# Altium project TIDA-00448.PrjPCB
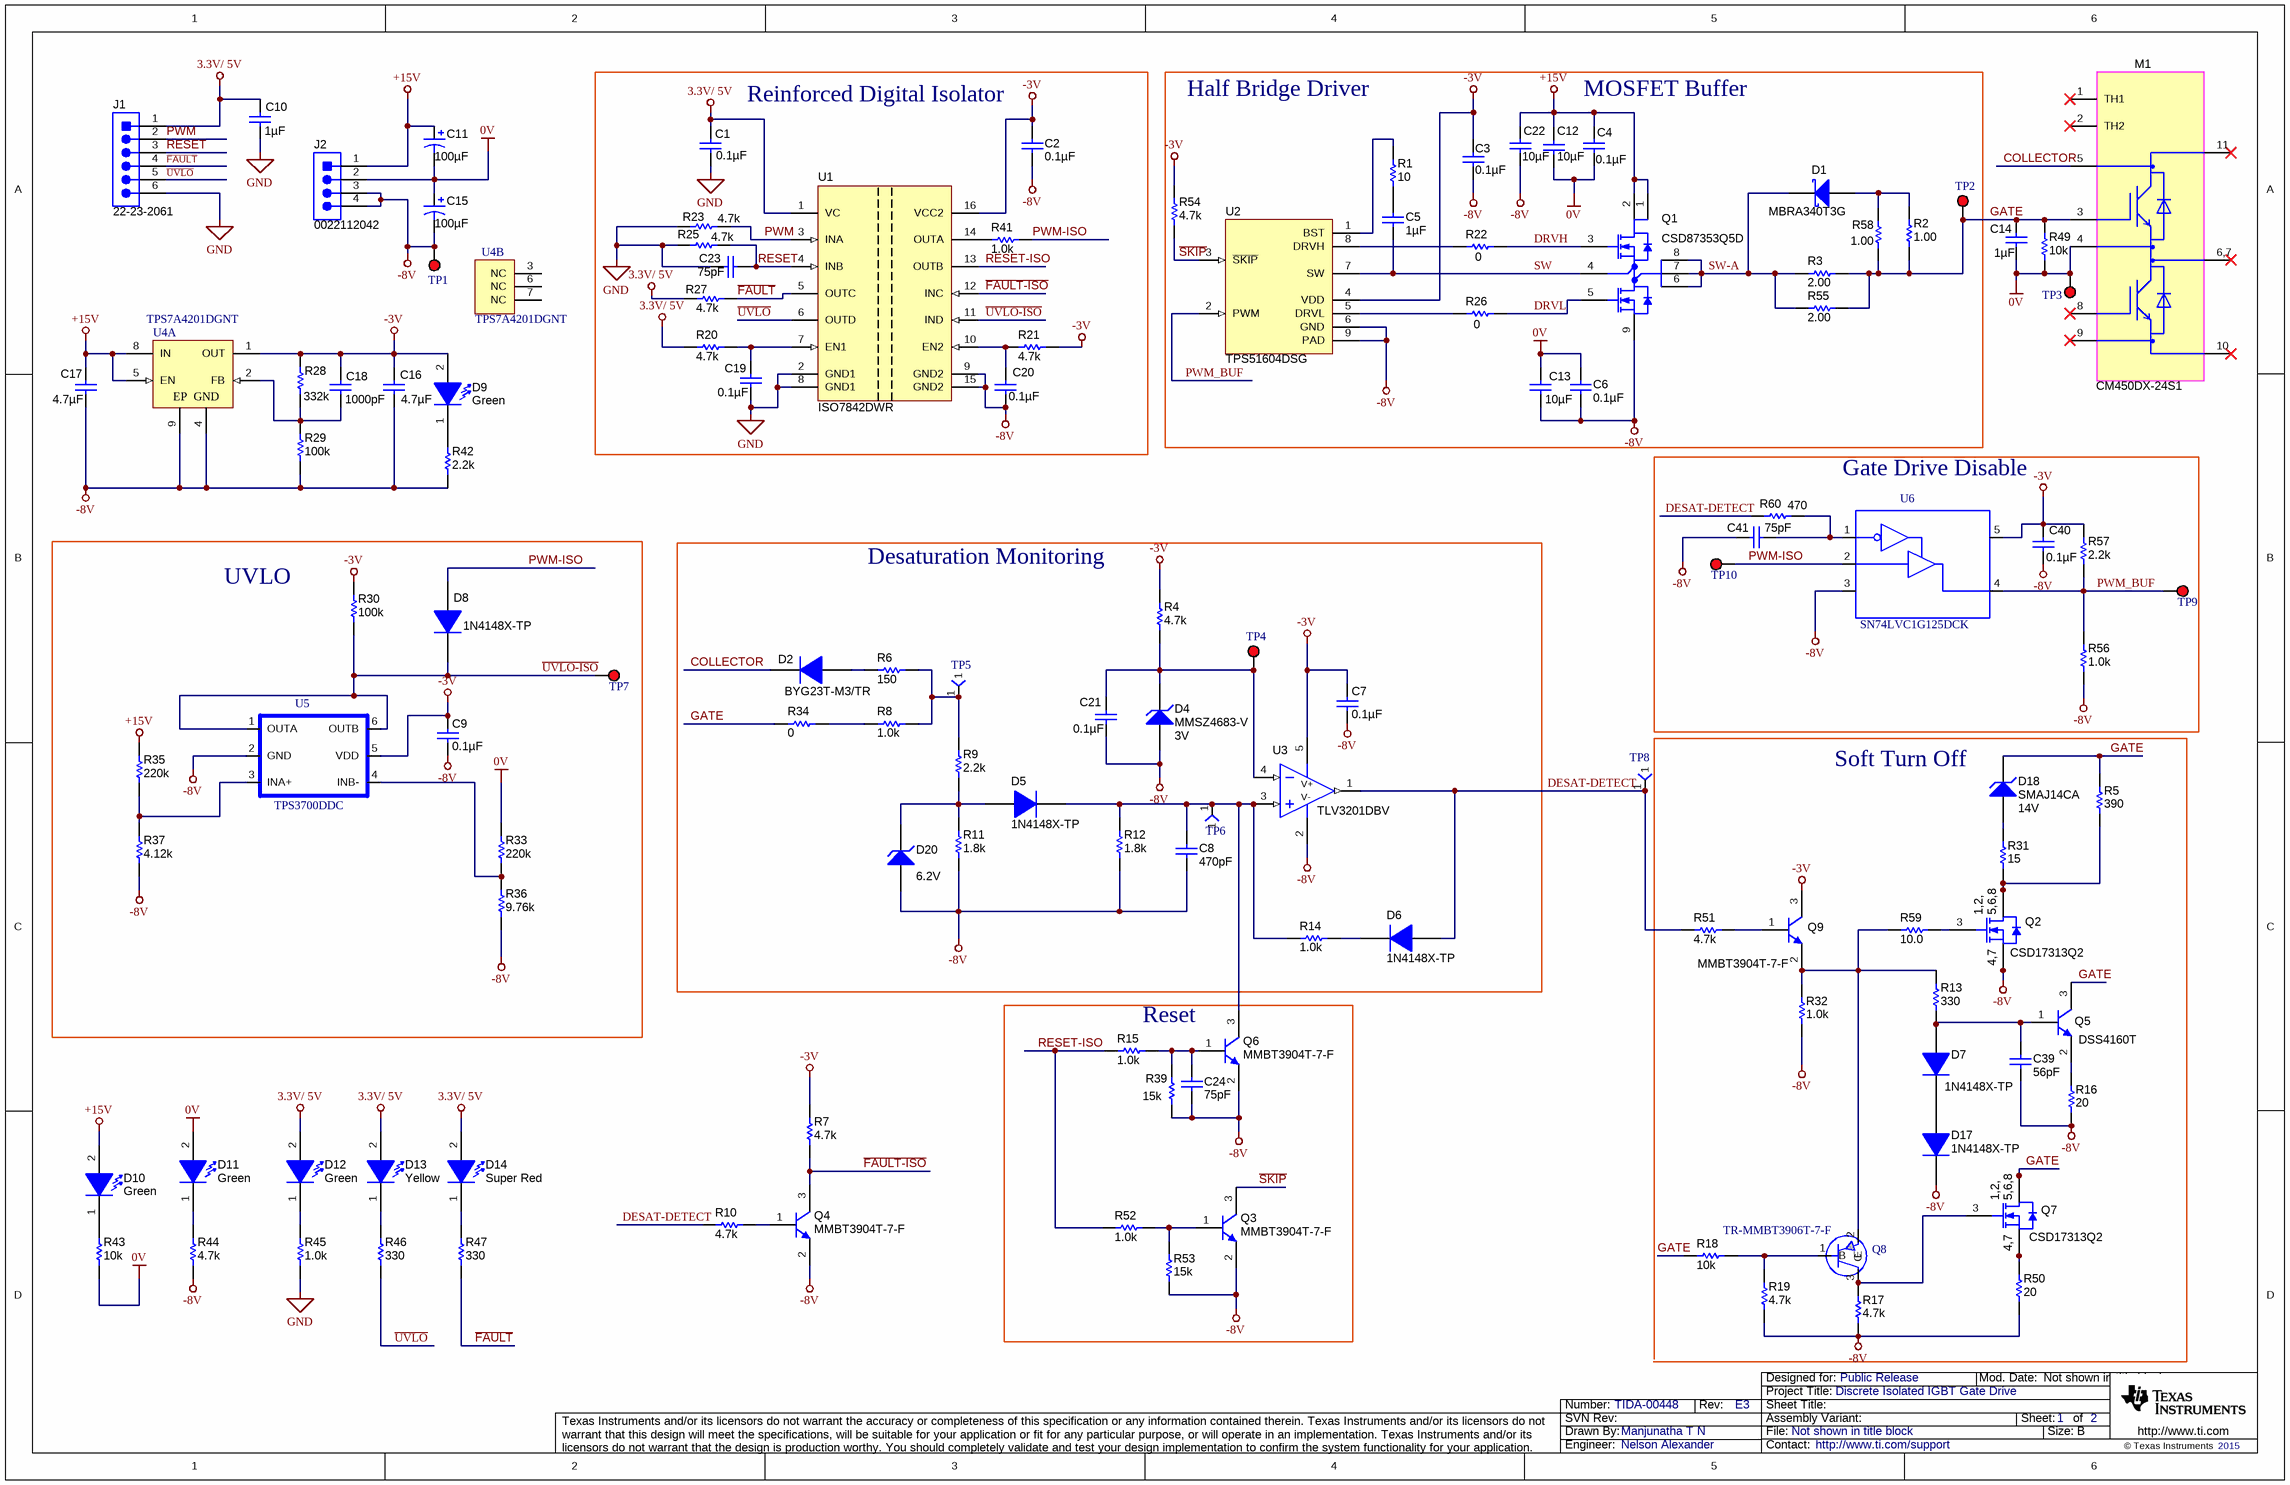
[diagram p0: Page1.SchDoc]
CopyrightYear: 2015; PCB_Layout: Manjunatha T N; PCB_Rev: E3; PRJ_Customer: Public Release; PRJ_Engineer: Nelson Alexander; PRJ_Number: TIDA-00448; PRJ_Title: Discrete Isolated IGBT Gate Drive; SCH_Rev: E3; TechSupport: http://www.ti.com/support
2 sheets, 141 parts. Net scope: global (net labels, ports and power ports of the same name join across sheets).
Board file: TIDA-00448_E3.PcbDoc
Sheets:
  Page1.SchDoc
  Page2_Hardware_ANSI-B.SchDoc

## Sheet Page1.SchDoc
size 431 x 279 mm; Date: Not shown in title block; ApprovedBy: Not shown in title block; CheckedBy: Not shown in title block; Author: Not shown in title block; CompanyName: Not shown in title block; DrawnBy: Manjunatha T N; Engineer: Not shown in title block; Organization: Not shown in title block; Address1: Not shown in title block; Address2: Not shown in title block; Address3: Not shown in title block; Address4: Not shown in title block; DocumentNumber: 4; Revision: Use project parameter SCH_Rev; SheetNumber: 1; SheetTotal: 2; PageSetup: Record=PageOptions¦CenterHorizontal=True¦CenterVertical=True¦PrintScale=0.62¦XCorrection=1.00¦YCorrection=1.00¦PrintKind=0¦BorderSize=5000000¦LeftOffset=0¦BottomOffset=0¦Orientation=2¦PaperLength=1000¦PaperWidth=1000¦Scale=100¦PaperSource=15¦PrintQuality=600¦MediaType=1¦DitherType=10¦PaperKind=Letter¦PrintScaleMode=1

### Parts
C1  ValueDisplayed: 0.1µF  [0603]  (hidden comment: 06035C104KAT2A)
C2  ValueDisplayed: 0.1µF  [0603]  (hidden comment: 06035C104KAT2A)
C3  ValueDisplayed: 0.1µF  [0603]  (hidden comment: 06035C104KAT2A)
C4  ValueDisplayed: 0.1µF  [0603]  (hidden comment: 06035C104KAT2A)
C5  ValueDisplayed: 1µF  [0603]  (hidden comment: UMK107AB7105KA-T)
C6  ValueDisplayed: 0.1µF  [0603]  (hidden comment: 06035C104KAT2A)
C7  ValueDisplayed: 0.1µF  [0603]  (hidden comment: 06035C104KAT2A)
C8  ValueDisplayed: 470pF  [0603]  (hidden comment: 06035A471JAT2A)
C9  ValueDisplayed: 0.1µF  [0603]  (hidden comment: 06035C104KAT2A)
C10  ValueDisplayed: 1µF  [0805_HV]  (hidden comment: 08055C105KAT2A)
C11  ValueDisplayed: 100µF  [SM_RADIAL_6.3BMM]  (hidden comment: UUD1E101MCL1GS)
C12  ValueDisplayed: 10µF  [1206]  (hidden comment: GMK316AB7106KL)
C13  ValueDisplayed: 10µF  [1206]  (hidden comment: GMK316AB7106KL)
C14  ValueDisplayed: 1µF  [0805_HV]  (hidden comment: DNP)
C15  ValueDisplayed: 100µF  [SM_RADIAL_6.3BMM]  (hidden comment: UUD1E101MCL1GS)
C16  ValueDisplayed: 4.7µF  [1206_190]  (hidden comment: UMK316AB7475KL-T)
C17  ValueDisplayed: 4.7µF  [1206_190]  (hidden comment: UMK316AB7475KL-T)
C18  ValueDisplayed: 1000pF  [0603]  (hidden comment: 06035A102KAT2A)
C19  ValueDisplayed: 0.1µF  [0603]  (hidden comment: 06035C104KAT2A)
C20  ValueDisplayed: 0.1µF  [0603]  (hidden comment: 06035C104KAT2A)
C21  ValueDisplayed: 0.1µF  [0603]  (hidden comment: 06035C104KAT2A)
C22  ValueDisplayed: 10µF  [1206]  (hidden comment: GMK316AB7106KL)
C23  ValueDisplayed: 75pF  [0603]  (hidden comment: GRM1885C1H750JA01D)
C24  ValueDisplayed: 75pF  [0603]  (hidden comment: GRM1885C1H750JA01D)
C39  ValueDisplayed: 56pF  [0603]  (hidden comment: 06035A560FAT2A)
C40  ValueDisplayed: 0.1µF  [0603]  (hidden comment: 06035C104KAT2A)
C41  ValueDisplayed: 75pF  [0603]  (hidden comment: GRM1885C1H750JA01D)
D1  MBRA340T3G  [SMA]
D2  BYG23T-M3/TR  [SMA]
D4  MMSZ4683-V  value 3V  [SOD-123]
D5  1N4148X-TP  [SOD-523]
D6  1N4148X-TP  [SOD-523]
D7  1N4148X-TP  [SOD-523]
D8  1N4148X-TP  [SOD-523]
D9  value Green  [WL-SMCW_GREEN]  (hidden comment: 150060GS75000)
D10  value Green  [WL-SMCW_GREEN]  (hidden comment: 150060GS75000)
D11  value Green  [WL-SMCW_GREEN]  (hidden comment: 150060GS75000)
D12  value Green  [WL-SMCW_GREEN]  (hidden comment: 150060GS75000)
D13  value Yellow  [WL-SMCW_YELLOW]  (hidden comment: 150060YS75000)
D14  value Super Red  [WL-SMCW_RED]  (hidden comment: 150060SS75000)
D17  1N4148X-TP  [SOD-523]
D18  SMAJ14CA  value 14V  [SMA]
D20  value 6.2V  [sod-323]  (hidden comment: MMSZ5234BS-7-F)
J1  22-23-2061  [Molex_22-23-2061]
J2  0022112042  [CONN_22112042]
M1  CM450DX-24S1  [MITSUBISHI_CM450DX-24S1]
Q1  CSD87353Q5D  [DQY0008A]
Q2  CSD17313Q2  [TRANS_NexFET_Q2]
Q3  MMBT3904T-7-F  [SOT-523]
Q4  MMBT3904T-7-F  [SOT-523]
Q5  DSS4160T  [SOT-23]
Q6  MMBT3904T-7-F  [SOT-523]
Q7  CSD17313Q2  [TRANS_NexFET_Q2]
Q8  TR-MMBT3906T-7-F  [SOT-523]
Q9  MMBT3904T-7-F  [SOT-523]
R1  ValueDisplayed: 10  [0603]  (hidden comment: CRCW060310R0JNEA)
R2  ValueDisplayed: 1.00  [2512]  (hidden comment: CRCW25121R00FKEG)
R3  ValueDisplayed: 2.00  [2512]  (hidden comment: CRCW25122R00FKEG)
R4  ValueDisplayed: 4.7k  [0603]  (hidden comment: RC0603JR-074K7L)
R5  ValueDisplayed: 390  [0603]  (hidden comment: CRCW0603390RJNEA)
R6  ValueDisplayed: 150  [0603]  (hidden comment: CRCW0603150RJNEA)
R7  ValueDisplayed: 4.7k  [0603]  (hidden comment: RC0603JR-074K7L)
R8  ValueDisplayed: 1.0k  [0603]  (hidden comment: CRCW06031K00JNEA)
R9  ValueDisplayed: 2.2k  [0603]  (hidden comment: CRCW06032K20JNEA)
R10  ValueDisplayed: 4.7k  [0603]  (hidden comment: RC0603JR-074K7L)
R11  ValueDisplayed: 1.8k  [0603]  (hidden comment: CRCW06031K80JNEA)
R12  ValueDisplayed: 1.8k  [0603]  (hidden comment: CRCW06031K80JNEA)
R13  ValueDisplayed: 330  [0603]  (hidden comment: CRCW0603330RJNEA)
R14  ValueDisplayed: 1.0k  [0603]  (hidden comment: CRCW06031K00JNEA)
R15  ValueDisplayed: 1.0k  [0603]  (hidden comment: CRCW06031K00JNEA)
R16  ValueDisplayed: 20  [0603]  (hidden comment: CRCW060320R0JNEA)
R17  ValueDisplayed: 4.7k  [0603]  (hidden comment: RC0603JR-074K7L)
R18  ValueDisplayed: 10k  [0603]  (hidden comment: CRCW060310K0JNEA)
R19  ValueDisplayed: 4.7k  [0603]  (hidden comment: RC0603JR-074K7L)
R20  ValueDisplayed: 4.7k  [0603]  (hidden comment: RC0603JR-074K7L)
R21  ValueDisplayed: 4.7k  [0603]  (hidden comment: RC0603JR-074K7L)
R22  ValueDisplayed: 0  [0603]  (hidden comment: CRCW06030000Z0EA)
R23  ValueDisplayed: 4.7k  [0603]  (hidden comment: RC0603JR-074K7L)
R25  ValueDisplayed: 4.7k  [0603]  (hidden comment: RC0603JR-074K7L)
R26  ValueDisplayed: 0  [0603]  (hidden comment: CRCW06030000Z0EA)
R27  ValueDisplayed: 4.7k  [0603]  (hidden comment: RC0603JR-074K7L)
R28  ValueDisplayed: 332k  [0603]  (hidden comment: CRCW0603332KFKEA)
R29  ValueDisplayed: 100k  [0603]  (hidden comment: CRCW0603100KFKEA)
R30  ValueDisplayed: 100k  [0603]  (hidden comment: CRCW0603100KJNEA)
R31  ValueDisplayed: 15  [0603]  (hidden comment: CRCW060315R0JNEA)
R32  ValueDisplayed: 1.0k  [0603]  (hidden comment: CRCW06031K00JNEA)
R33  ValueDisplayed: 220k  [0603]  (hidden comment: RC0603FR-07220KL)
R34  ValueDisplayed: 0  [0402]  (hidden comment: CRCW04020000Z0ED)
R35  ValueDisplayed: 220k  [0603]  (hidden comment: RC0603FR-07220KL)
R36  ValueDisplayed: 9.76k  [0603]  (hidden comment: RC0603FR-079K76L)
R37  ValueDisplayed: 4.12k  [0603]  (hidden comment: RC0603FR-074K12L)
R39  ValueDisplayed: 15k  [0603]  (hidden comment: RC0603JR-0715KL)
R41  ValueDisplayed: 1.0k  [0603]  (hidden comment: CRCW06031K00JNEA)
R42  ValueDisplayed: 2.2k  [0603]  (hidden comment: RC0603JR-072K2L)
R43  ValueDisplayed: 10k  [0603]  (hidden comment: CRCW060310K0JNEA)
R44  ValueDisplayed: 4.7k  [0603]  (hidden comment: RC0603JR-074K7L)
R45  ValueDisplayed: 1.0k  [0603]  (hidden comment: CRCW06031K00JNEA)
R46  ValueDisplayed: 330  [0603]  (hidden comment: CRCW0603330RJNEA)
R47  ValueDisplayed: 330  [0603]  (hidden comment: CRCW0603330RJNEA)
R49  ValueDisplayed: 10k  [0603]  (hidden comment: CRCW060310K0JNEA)
R50  ValueDisplayed: 20  [0603]  (hidden comment: CRCW060320R0JNEA)
R51  ValueDisplayed: 4.7k  [0603]  (hidden comment: RC0603JR-074K7L)
R52  ValueDisplayed: 1.0k  [0603]  (hidden comment: CRCW06031K00JNEA)
R53  ValueDisplayed: 15k  [0603]  (hidden comment: RC0603JR-0715KL)
R54  ValueDisplayed: 4.7k  [0603]  (hidden comment: RC0603JR-074K7L)
R55  ValueDisplayed: 2.00  [2512]  (hidden comment: CRCW25122R00FKEG)
R56  ValueDisplayed: 1.0k  [0603]  (hidden comment: CRCW06031K00JNEA)
R57  ValueDisplayed: 2.2k  [0603]  (hidden comment: RC0603JR-072K2L)
R58  ValueDisplayed: 1.00  [2512]  (hidden comment: CRCW25121R00FKEG)
R59  ValueDisplayed: 10.0  [0603]  (hidden comment: CRCW060310R0FKEAHP)
R60  ValueDisplayed: 470  [0603]  (hidden comment: CRCW0603470RJNEA)
TP1  5000  [Keystone5000]  (value not drawn)
TP2  5000  [Keystone5000]  (value not drawn)
TP3  5000  [Keystone5000]  (value not drawn)
TP4  5000  [Keystone5000]  (value not drawn)
TP5  TP_40_SMT  [TP_40_SMT]  (value not drawn)
TP6  TP_40_SMT  [TP_40_SMT]  (value not drawn)
TP7  5000  [Keystone5000]  (value not drawn)
TP8  TP_40_SMT  [TP_40_SMT]  (value not drawn)
TP9  5000  [Keystone5000]  (value not drawn)
TP10  5000  [Keystone5000]  (value not drawn)
U1  ISO7842DWR  [DW0016B_N]
U2  TPS51604DSG  [DSG0008A]
U3  TLV3201DBV  [DBV0005A_N]
U4  TPS7A4201DGNT  [DGN0008B_N]  (parts A,B of 2)
U5  TPS3700DDC  [SOT23-6]
U6  SN74LVC1G125DCK  [SOP_5P.65MM(DCK)]

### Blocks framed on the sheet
Reinforced Digital Isolator: C1 C2 C19 C20 C23 R20 R21 R23 R25 R27 R41 U1
Gate Drive Disable: C40 C41 R56 R57 R60 TP9 TP10 U6
UVLO: C9 D8 R30 R33 R35-R37 TP7 U5
Desaturation Monitoring: C7 C8 C21 D2 D4-D6 D20 R4 R6 R8 R9 R11 R12 R14 R34 TP4-TP6 U3
Reset: C24 Q3 Q6 R15 R39 R52 R53

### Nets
0V: C4.2 C6.1 C11.2(-) C12.2 C13.1 C14.2 C15.1(+) D11.2(A) J2.2 M1.4(ES1) R33.2 R43.2 R49.1 TP3.1
3.3V/ 5V: C1.1 C10.1 D12.2(A) D13.2(A) D14.2(A) J1.1 R20.2 R27.2 U1.1(VC)
+15V: C4.1 C11.1(+) C12.1 C17.1 C22.1 D10.2(A) J2.1 Q1.1(VIN) Q1.2(VIN) R35.2 U4.5(EN) U4.8(IN)
-3V: C2.1 C3.1 C7.1 C9.1 C16.1 C18.1 C40.1 D9.2(A) Q9.3(C) R4.2 R7.2 R21.1 R28.2 R30.2 R54.1 R57.2 U1.16(VCC2) U2.4(VDD) U3.5(V+) U4.1(OUT) U5.5(VDD) U6.5(VCC)
-8V: C2.2 C3.2 C6.2 C7.2 C8.2 C9.2 C13.2 C15.2(-) C16.2 C17.2 C20.2 C21.2 C22.2 C24.1 C39.2 C40.2 C41.1 D4.2(A) D17.1(K) D20.2(A) J2.3 J2.4 Q1.9(PGND) Q2.4(S) Q2.7(S) Q3.2(E) Q4.2(E) Q6.2(E) R11.1 R12.1 R16.1 R17.1 R19.1 R29.1 R32.1 R36.1 R37.1 R39.2 R42.1 R44.1 R50.1 R53.2 R56.1 TP1.1 U1.9(GND2) U1.15(GND2) U2.6(GND) U2.9(PAD) U3.2(V-) U4.4(GND) U4.9(EP) U5.2(GND) U6.3(GND)
GND: C1.2 C10.2 C19.2 C23.1 J1.6 R23.2 R25.2 R45.1 U1.2(GND1) U1.8(GND1)
~{SKIP}: Q3.3(C) R54.2 U2.3(~{SKIP})
COLLECTOR: D2.1(K) M1.5(CS1)
DESAT-DETECT: D6.2(A) R10.1 R51.1 R60.1 TP8.1 U3.1(OUT)
DRVH: Q1.3(TG) R22.2
DRVL: Q1.5(BG) R26.2
~{FAULT}: J1.4 R27.1 R47.1 U1.5(OUTC)
~{FAULT-ISO}: Q4.3(C) R7.1 U1.12(INC)
GATE: C14.1 D18.1(K) M1.3(G1) Q5.3(C) Q7.1(D) Q7.2(D) Q7.5(D) Q7.6(D) Q7.8(D) R2.1 R3.2 R5.2 R18.1 R34.1 R49.2 R55.2 R58.1 TP2.1
PWM: J1.2 R23.1 U1.3(INA)
PWM-ISO: D8.2(A) R41.1 TP10.1 U6.2(A)
PWM_BUF: R56.2 R57.1 TP9.1 U2.2(PWM) U6.4(Y)
RESET: C23.2 J1.3 R25.1 U1.4(INB)
RESET-ISO: R15.1 R52.1 U1.13(OUTB)
SW: C5.2 Q1.4(TGR) U2.7(SW)
SW-A: D1.1(K) Q1.6(VSW) Q1.7(VSW) Q1.8(VSW) R3.1 R55.1
~{UVLO}: J1.5 R46.1 U1.6(OUTD)
~{UVLO-ISO}: D8.1(K) R30.1 TP7.1 U1.11(IND) U5.1(OUTA) U5.6(OUTB)
NetC5_1: C5.1 R1.1
NetC8_1: C8.1 D5.1(K) Q6.3(C) R12.2 R14.1 TP6.1 U3.3(IN+)
NetC18_2: C18.2 R28.1 R29.2 U4.2(FB)
NetC19_1: C19.1 R20.1 U1.7(EN1)
NetC20_1: C20.1 R21.2 U1.10(EN2)
NetC21_1: C21.1 D4.1(K) R4.1 TP4.1 U3.4(IN-)
NetC24_2: C24.2 Q6.1(B) R15.2 R39.1
NetC39_1: C39.1 D7.2(A) Q5.1(B) R13.1
NetC41_2: C41.2 R60.2 U6.1(~OE)
NetD1_2: D1.2(A) R2.2 R58.2
NetD2_2: D2.2(A) R6.1
NetD5_2: D5.2(A) D20.1(K) R9.1 R11.2
NetD6_1: D6.1(K) R14.2
NetD7_1: D7.1(K) D17.2(A)
NetD9_1: D9.1(K) R42.2
NetD10_1: D10.1(K) R43.1
NetD11_1: D11.1(K) R44.2
NetD12_1: D12.1(K) R45.2
NetD13_1: D13.1(K) R46.2
NetD14_1: D14.1(K) R47.2
NetD18_2: D18.2(A) R31.2
NetQ2_1: Q2.1(D) Q2.2(D) Q2.5(D) Q2.6(D) Q2.8(D) R5.1 R31.1
NetQ2_3: Q2.3(G) R59.1
NetQ3_1: Q3.1(B) R52.2 R53.1
NetQ4_1: Q4.1(B) R10.2
NetQ5_2: Q5.2(E) R16.2
NetQ7_3: Q7.3(G) Q8.3(C) R17.2
NetQ7_4: Q7.4(S) Q7.7(S) R50.2
NetQ8_1: Q8.1(B) R18.2 R19.2
NetQ8_2: Q8.2(E) Q9.2(E) R13.2 R32.2 R59.2
NetQ9_1: Q9.1(B) R51.2
NetR1_2: R1.2 U2.1(BST)
NetR6_2: R6.2 R8.2 R9.2 TP5.1
NetR8_1: R8.1 R34.2
NetR22_1: R22.1 U2.8(DRVH)
NetR26_1: R26.1 U2.5(DRVL)
NetR33_1: R33.1 R36.2 U5.4(INB-)
NetR35_1: R35.1 R37.2 U5.3(INA+)
NetR41_2: R41.2 U1.14(OUTA)

Not connected (* = marked no-connect by the designer): M1 1(TH1)* 2(TH2)* 6,7(C2E1)* 8(G2)* 9(ES2)* 10(E2)* 11*; U4 3(NC) 6(NC) 7(NC)

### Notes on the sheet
- Half Bridge Driver
- MOSFET Buffer
- (near D18) Soft Turn Off

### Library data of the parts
C1-C4 C6 C7 C9 C19-C21 C40 = 06035C104KAT2A: CAP, CERM, 0.1 µF, 50 V, +/- 10%, X7R, 0603; Manufacturer: AVX; Polarized: N; CompType: Capacitor; Value: 0.1uF; U/M: EA; Cap_F: 0.0000001; Tolerance_%: 10; Value1: Unknown; VDC_V: 50; Value2: 50V; TaMin_C: -55; TaMax_C: 125
C5 = UMK107AB7105KA-T: CAP, CERM, 1 µF, 50 V, +/- 10%, X7R, 0603; Manufacturer: Taiyo Yuden; Polarized: N; CompType: Capacitor; Value: 1uF; U/M: EA; Cap_F: 0.000001; Tolerance_%: 10; Value1: Unknown; VDC_V: 50; Value2: 50V; TaMin_C: -55; TaMax_C: 125
C8 = 06035A471JAT2A: CAP, CERM, 470 pF, 50 V, +/- 5%, C0G/NP0, 0603; Manufacturer: AVX; Polarized: N; CompType: Capacitor; Value: 470pF; U/M: EA; Cap_F: 0.00000000047; Tolerance_%: 5; ESR_ohm: 0.063; Value1: 0.063 ohm; VDC_V: 50; Value2: 50V; TaMin_C: -55; TaMax_C: 125
C10 = 08055C105KAT2A: CAP, CERM, 1 µF, 50 V, +/- 10%, X7R, 0805; Manufacturer: AVX; Polarized: N; CompType: Capacitor; Value: 1uF; U/M: EA; Cap_F: 0.000001; Tolerance_%: 10; Value1: Unknown; VDC_V: 50; Value2: 50V; TaMin_C: -55; TaMax_C: 125; Cap_Case: 0805
C11 C15 = UUD1E101MCL1GS: CAP, AL, 100 µF, 25 V, +/- 20%, 0.34 ohm, SMD; Manufacturer: Nichicon; Polarized: Y; CompType: Capacitor; Value: 100uF; U/M: EA; Cap_F: 0.0001; Tolerance_%: 20; VDC_V: 25; Value2: 25V; ESR_ohm: 0.34; IRMS_A: 0.28; TaMin_C: -55; TaMax_C: 105; Cap_Case: 6.3x7.7
C12 C13 C22 = GMK316AB7106KL: CAP, CERM, 10 µF, 35 V, +/- 10%, X7R, 1206; Manufacturer: Taiyo Yuden; Polarized: N; CompType: Capacitor; Value: 10uF; U/M: EA; Cap_F: 0.00001; Tolerance_%: 10; Value1: Unknown; VDC_V: 35; Value2: 35V; TaMin_C: -55; TaMax_C: 125
C14 = 08055C105KAT2A: Manufacturer: AVX; Polarized: N; CompType: Capacitor; Value: 1uF; U/M: EA; Cap_F: 0.000001; Tolerance_%: 10; Value1: Unknown; VDC_V: 50; Value2: 50V; TempCo: X7R; TaMin_C: -55; TaMax_C: 125; Cap_Case: 0805
C16 C17 = UMK316AB7475KL-T: CAP, CERM, 4.7 µF, 50 V, +/- 10%, X7R, 1206_190; Manufacturer: Taiyo Yuden; Polarized: N; CompType: Capacitor; Value: 4.7uF; U/M: EA; Cap_F: 0.0000047; Tolerance_%: 10; Value1: Unknown; VDC_V: 50; Value2: 50V; TaMin_C: -55; TaMax_C: 125; Cap_Case: 1206
C18 = 06035A102KAT2A: CAP, CERM, 1000 pF, 50 V, +/- 10%, C0G/NP0, 0603; Manufacturer: AVX; Polarized: N; CompType: Capacitor; Value: 1000pF; U/M: EA; Cap_F: 0.000000001; Tolerance_%: 10; ESR_ohm: 0.048; Value1: 0.048 ohm; VDC_V: 50; Value2: 50V; TaMin_C: -55; TaMax_C: 125
C23 C24 C41 = GRM1885C1H750JA01D: CAP, CERM, 75 pF, 50 V, +/- 5%, C0G/NP0, 0603; Manufacturer: MuRata; Polarized: N; CompType: Capacitor; Value: 75pF; U/M: EA; Cap_F: 0.000000000075; Tolerance_%: 5; Value1: Unknown; VDC_V: 50; Value2: 50V; TaMin_C: -55; TaMax_C: 125
C39 = 06035A560FAT2A: CAP, CERM, 56 pF, 50 V, +/- 1%, C0G/NP0, 0603; Manufacturer: AVX; Polarized: N; CompType: Capacitor; Value: 56pF; U/M: EA; Cap_F: 0.000000000056; Tolerance_%: 1; Value1: Unknown; VDC_V: 50; Value2: 50V; TaMin_C: -55; TaMax_C: 125
D1 = MBRA340T3G: Diode, Schottky, 40 V, 3 A, SMA; Manufacturer: ON Semiconductor; U/M: EA; Vf_V: 0.415; Value: 40V; Value1: 3A; Value2: 0.415V; Io_A: 3; Vr_V: 40; RJC_CperW: 15
D2 = BYG23T-M3/TR: Diode, Ultrafast, 1300 V, 1 A, SMA; Manufacturer: Vishay-Semiconductor; U/M: EA; Vf_V: 1.9; Value: 1300V; Value1: 1A; Value2: 1.9V; Io_A: 1; Vr_V: 1300; TJmax_C: 150
D4 = MMSZ4683-V: Diode, Zener, 3 V, 500 mW, SOD-123; Manufacturer: Vishay-Semiconductor; SymbolCreator: a0412235; U/M: EA; Power_W: 0.5; Vz_V: 3; Value1: 0.5W; RJA_CperW: 67
D5-D8 D17 = 1N4148X-TP: Diode, Switching, 75 V, 0.3 A, SOD-523; Manufacturer: Micro Commercial Components; U/M: EA; Vf_V: 1.25; Value: 75V; Value1: 0.3A; Value2: 1.25V; Io_A: 0.3; Vr_V: 75; TJmax_C: 150
D9-D12 = 150060GS75000: LED, Green, SMD; Manufacturer: Wurth Elektronik; Type: InGaN; Vf_V: 3.2; Value2: 3.2V; Io_A: 0.02; Tjmax_C: 85; Value1: W; Angle: 140; U/M: EA
D13 = 150060YS75000: LED, Yellow, SMD; Manufacturer: Wurth Elektronik; Type: AlInGaP; Vf_V: 2; Value2: 2V; Io_A: 0.02; Value1: W; U/M: EA
D14 = 150060SS75000: LED, Super Red, SMD; Manufacturer: Wurth Elektronik; Type: AlInGaP; Vf_V: 1.9; Value2: 1.9V; Io_A: 0.02; Value1: W; U/M: EA
D18 = 3SMAJ5926B: Diode, Zener, 11 V, DO-214AC; Manufacturer: Littelfuse Inc.; SymbolCreator: x0199378
D20 = MMSZ5234BS-7-F: Diode, Zener, 6.2 V, 200 mW, SOD-323; Manufacturer: Diodes Inc.; SymbolCreator: a0412235; U/M: EA; Power_W: 0.2; Vz_V: 6.2; Value1: 0.2W; RJA_CperW: 350
J1 = 22-23-2061: Header, 2.54 mm, 6x1, Tin, TH; Manufacturer: Molex; SymbolCreator: a0412235; U/M: EA
J2 = 0022112042: Header (friction lock), 100mil, 4x1, Gold, TH; Manufacturer: Molex; SymbolCreator: a0412235; U/M: EA
M1 = CM450DX-24S1: IGBT, MOD NX, 450A, 1200V, DUAL; Manufacturer: POWEREX INC; SymbolCreator: x0199378
Q1 = CSD87350Q5D: Synchronous Buck NexFET Power Block, DQY0008A; Manufacturer: Texas Instruments; SymbolCreator: a0799628; CompType: IC; U/M: EA
Q2 Q7 = CSD17313Q2: MOSFET, N-CH, 30 V, 5 A, SON 2x2mm; Manufacturer: Texas Instruments; Alternate Manufacturer: None; U/M: EA; ChType: N; Value: 30V; VdsMax_V: 30; Value1: 0.026 ohm; Rdson45_ohm: 0.026; Value2: 2.1 nC; QgTyp_nC: 2.1; Vgs_V: 10; IdsMax_A: 5
Q3 Q4 Q6 Q9 = MMBT3904T-7-F, Diodes Inc.: Transistor, NPN, 40 V, 0.2 A, SOT-523; CompType: BJT; PNP: 0; NPN: 1; Vceo_V: 40; Vcesat1_V: 0.2; Value: 40 V; Value1: 0.2 A; HfeMax: 300; TaMin_C: -55; TaMax_C: 150; U/M: EA
Q5 = DSS4160T: TRANSISTOR, NPN, 60V, 1A, SOT23-3; Manufacturer: DIODES INCORPORATED; CompType: Bipolar Transistor; SymbolCreator: x0199378
Q8 = TR-MMBT3906T-7-F: Bipolar, PNP, -40V, -200mA, -200mW; Manufacturer: Diodes; Area: 11904
R1 = CRCW060310R0JNEA: RES, 10, 5%, 0.1 W, 0603; Manufacturer: Vishay-Dale; CompType: Resistor; Value: 10; Value_Code: 10R0; Tolerance_%: 5; Power_W: 0.1; Value2: 0.1W; VDC_V: 75; TempCo: 200 ppm/C; EIA_Code: E24; U/M: EA
R2 R58 = CRCW25121R00FKEG: RES, 1.00, 1%, 1 W, 2512; Manufacturer: Vishay-Dale; CompType: Resistor; Value: 1.00; Res_ohm: 1; Value_Code: 1R00; Value2: 1W; VDC_V: 500; TempCo: 100 ppm/C; EIA_Code: E96; U/M: EA
R3 R55 = CRCW25122R00FKEG: RES, 2.00, 1%, 1 W, 2512; Manufacturer: Vishay-Dale; CompType: Resistor; Value: 2.00; Res_ohm: 2; Value_Code: 2R00; Tolerance_%: 1; Value2: 1W; VDC_V: 500; TempCo: 100 ppm/C; EIA_Code: E96; U/M: EA
R4 R7 R10 R17 R19-R21 R23 R25 R27 R44 R51 R54 = RC0603JR-074K7L: RES, 4.7 k, 5%, 0.1 W, 0603; Manufacturer: Yageo America; CompType: Resistor; Value: 4.7k; Res_ohm: 4700; Value_Code: 4k70; Tolerance_%: 5; Power_W: 0.1; Value2: 0.1W; VDC_V: 50; TempCo: 100 ppm/C; EIA_Code: E24; U/M: EA
R5 = CRCW0603390RJNEA: RES, 390, 5%, 0.1 W, 0603; Manufacturer: Vishay-Dale; CompType: Resistor; Value: 390; Value_Code: 390R; Tolerance_%: 5; Power_W: 0.1; Value2: 0.1W; VDC_V: 75; TempCo: 200 ppm/C; EIA_Code: E24; U/M: EA
R6 = CRCW0603150RJNEA: RES, 150, 5%, 0.1 W, 0603; Manufacturer: Vishay-Dale; CompType: Resistor; Value: 150; Value_Code: 150R; Tolerance_%: 5; Power_W: 0.1; Value2: 0.1W; VDC_V: 75; TempCo: 200 ppm/C; EIA_Code: E24; U/M: EA
R8 R14 R15 R32 R41 R45 R52 R56 = CRCW06031K00JNEA: RES, 1.0 k, 5%, 0.1 W, 0603; Manufacturer: Vishay-Dale; CompType: Resistor; Value: 1.0k; Res_ohm: 1000; Value_Code: 1k00; Tolerance_%: 5; Power_W: 0.1; Value2: 0.1W; VDC_V: 75; TempCo: 200 ppm/C; EIA_Code: E24; U/M: EA
R9 = CRCW06032K20JNEA: RES, 2.2 k, 5%, 0.1 W, 0603; Manufacturer: Vishay-Dale; CompType: Resistor; Value: 2.2k; Res_ohm: 2200; Value_Code: 2k20; Tolerance_%: 5; Power_W: 0.1; Value2: 0.1W; VDC_V: 75; TempCo: 200 ppm/C; EIA_Code: E24; U/M: EA
R11 R12 = CRCW06031K80JNEA: RES, 1.8 k, 5%, 0.1 W, 0603; Manufacturer: Vishay-Dale; CompType: Resistor; Value: 1.8k; Res_ohm: 1800; Value_Code: 1k80; Tolerance_%: 5; Power_W: 0.1; Value2: 0.1W; VDC_V: 75; TempCo: 200 ppm/C; EIA_Code: E24; U/M: EA
R13 R46 R47 = CRCW0603330RJNEA: RES, 330, 5%, 0.1 W, 0603; Manufacturer: Vishay-Dale; CompType: Resistor; Value: 330; Value_Code: 330R; Tolerance_%: 5; Power_W: 0.1; Value2: 0.1W; VDC_V: 75; TempCo: 200 ppm/C; EIA_Code: E24; U/M: EA
R16 R50 = CRCW060320R0JNEA: RES, 20, 5%, 0.1 W, 0603; Manufacturer: Vishay-Dale; CompType: Resistor; Value: 20; Value_Code: 20R0; Tolerance_%: 5; Power_W: 0.1; Value2: 0.1W; VDC_V: 75; TempCo: 200 ppm/C; EIA_Code: E24; U/M: EA
R18 R43 R49 = CRCW060310K0JNEA: RES, 10 k, 5%, 0.1 W, 0603; Manufacturer: Vishay-Dale; CompType: Resistor; Value: 10k; Res_ohm: 10000; Value_Code: 10k0; Tolerance_%: 5; Power_W: 0.1; Value2: 0.1W; VDC_V: 75; TempCo: 200 ppm/C; EIA_Code: E24; U/M: EA
R22 R26 = CRCW06030000Z0EA: RES, 0, 5%, 0.1 W, 0603; Manufacturer: Vishay-Dale; CompType: Resistor; Value: 0; Value_Code: 0000; Tolerance_%: 5; Power_W: 0.1; Value2: 0.1W; VDC_V: 75; TempCo: 200 ppm/C; EIA_Code: E24; U/M: EA
R28 = CRCW0603332KFKEA: RES, 332 k, 1%, 0.1 W, 0603; Manufacturer: Vishay-Dale; CompType: Resistor; Value: 332k; Res_ohm: 332000; Tolerance_%: 1; Power_W: 0.1; Value2: 0.1W; VDC_V: 75; TempCo: 100 ppm/C; EIA_Code: E96; U/M: EA
R29 = CRCW0603100KFKEA: RES, 100 k, 1%, 0.1 W, 0603; Manufacturer: Vishay-Dale; CompType: Resistor; Value: 100k; Res_ohm: 100000; Tolerance_%: 1; Power_W: 0.1; Value2: 0.1W; VDC_V: 75; TempCo: 100 ppm/C; EIA_Code: E96; U/M: EA
R30 = CRCW0603100KJNEA: RES, 100 k, 5%, 0.1 W, 0603; Manufacturer: Vishay-Dale; CompType: Resistor; Value: 100k; Res_ohm: 100000; Tolerance_%: 5; Power_W: 0.1; Value2: 0.1W; VDC_V: 75; TempCo: 200 ppm/C; EIA_Code: E24; U/M: EA
R31 = CRCW060315R0JNEA: RES, 15, 5%, 0.1 W, 0603; Manufacturer: Vishay-Dale; CompType: Resistor; Value: 15; Value_Code: 15R0; Tolerance_%: 5; Power_W: 0.1; Value2: 0.1W; VDC_V: 75; TempCo: 200 ppm/C; EIA_Code: E24; U/M: EA
R33 R35 = RC0603FR-07220KL: RES, 220 k, 1%, 0.1 W, 0603; Manufacturer: Yageo America; CompType: Resistor; Value: 220k; Res_ohm: 220000; Tolerance_%: 1; Power_W: 0.1; Value2: 0.1W; VDC_V: 150; TempCo: 200 ppm/C; U/M: EA
R34 = CRCW04020000Z0ED: RES, 0, 5%, 0.063 W, 0402; Manufacturer: Vishay-Dale; CompType: Resistor; Value: 0; Value_Code: 0000; Tolerance_%: 5; Power_W: 0.063; Value2: 0.063W; VDC_V: 50; TempCo: 200 ppm/C; EIA_Code: E24; U/M: EA
R36 = RC0603FR-079K76L: RES, 9.76 k, 1%, 0.1 W, 0603; Manufacturer: Yageo America; CompType: Resistor; Value: 9.76k; Res_ohm: 9760; Value_Code: 9k76; Tolerance_%: 1; Power_W: 0.1; Value2: 0.1W; VDC_V: 150; TempCo: 200 ppm/C; EIA_Code: E96; U/M: EA
R37 = RC0603FR-074K12L: RES, 4.12 k, 1%, 0.1 W, 0603; Manufacturer: Yageo America; CompType: Resistor; Value: 4.12k; Res_ohm: 4120; Value_Code: 4k12; Tolerance_%: 1; Power_W: 0.1; Value2: 0.1W; VDC_V: 150; TempCo: 200 ppm/C; EIA_Code: E96; U/M: EA
R39 R53 = RC0603JR-0715KL: RES, 15 k, 5%, 0.1 W, 0603; Manufacturer: Yageo America; CompType: Resistor; Value: 15k; Res_ohm: 15000; Value_Code: 15k0; Tolerance_%: 5; Power_W: 0.1; Value2: 0.1W; VDC_V: 50; TempCo: 100 ppm/C; EIA_Code: E24; U/M: EA
R42 R57 = RC0603JR-072K2L: RES, 2.2 k, 5%, 0.1 W, 0603; Manufacturer: Yageo America; CompType: Resistor; Value: 2.2k; Res_ohm: 2200; Value_Code: 2k20; Tolerance_%: 5; Power_W: 0.1; Value2: 0.1W; VDC_V: 50; TempCo: 100 ppm/C; EIA_Code: E24; U/M: EA
R59 = CRCW060310R0FKEAHP: RES, 10.0, 1%, 0.25 W, 0603; Manufacturer: Vishay-Dale; CompType: Resistor; Value: 10.0; Res_ohm: 10; Value_Code: 10R0; Tolerance_%: 1; Power_W: 0.25; Value2: 0.25W; VDC_V: 75; TempCo: 100 ppm/C; EIA_Code: E96; U/M: EA
R60 = CRCW0603470RJNEA: RES, 470, 5%, 0.1 W, 0603; Manufacturer: Vishay-Dale; CompType: Resistor; Value: 470; Value_Code: 470R; Tolerance_%: 5; Power_W: 0.1; Value2: 0.1W; VDC_V: 75; TempCo: 200 ppm/C; EIA_Code: E24; U/M: EA
TP1-TP4 TP7 TP9 TP10 = 5000: Test Point, Miniature, Red, TH; Manufacturer: Keystone; CompType: Test Point Loop; U/M: EA
TP5 TP6 TP8 = TP_40_SMT: Test point, 40 mil SMT; Manufacturer: None; Value: None
U1 = ISO7842DWR: High-Performance, 8000 VPK Reinforced Quad Channel Digital Isolator, DW0016B; Manufacturer: Texas Instruments; SymbolCreator: Altium; CompType: IC; U/M: EA
U2 = TPS51604DSG: Synchronous Buck FET Driver Optimized for High-Frequency Applications, DSG0008A; Manufacturer: Texas Instruments; SymbolCreator: a0411947; CompType: IC; U/M: EA
U3 = TLV3201DBV: 40-ns, microPOWER, Push-Pull Output Comparators, DBV0005A; Manufacturer: Texas Instruments; CompType: IC; U/M: EA
U4 = TPS7A4201DGNT: Single Output LDO, 50 mA, Adjustable 1.175 to 26 V Output, 7 to 28 V Input, 8-pin MSOP (DGN), -40 to 125 degC, Green (RoHS & no Sb/Br); Manufacturer: Texas Instruments; Alternate Manufacturer: None; Alternate PartNumber: Equivalent; Accuracy(%): 1; Iout(Max)(A): 0.05; Iq(Typ)(mA): 0.02; SubFamily: Single Channel LDO; Vdo(Typ)(mV): 290; Vin(Max)(V): 28; Vin(Min)(V): 7; Vout Adj(Max)(V): 26; Vout Adj(Min)(V): 1.161
U5 = TPS3700DDC: IC,  High Voltage, Over-Under Voltage Supervisory; Manufacturer: TI; Alternate Manufacturer: None; Area: 23200
U6 = SN74LVC1G125DCK: IC, Single Bus Buffer Gate With 3-States Outputs, OE  Active Low; Manufacturer: TI; Alternate Manufacturer: None; Area: 19,500

## Sheet Page2_Hardware_ANSI-B.SchDoc
size 431 x 279 mm; Date: Not shown in title block; ApprovedBy: Not shown in title block; CheckedBy: Not shown in title block; Author: Not shown in title block; CompanyName: Not shown in title block; DrawnBy: Manjunatha T N; Engineer: Not shown in title block; Organization: Not shown in title block; Address1: Not shown in title block; Address2: Not shown in title block; Address3: Not shown in title block; Address4: Not shown in title block; DocumentNumber: 5; Revision: Use project parameter SCH_Rev; SheetNumber: 2; SheetTotal: 2; PageSetup: Record=PageOptions|CenterHorizontal=True|CenterVertical=True|PrintScale=1.00|XCorrection=1.00|YCorrection=1.00|PrintKind=0|BorderSize=5000000|LeftOffset=0|BottomOffset=0|Orientation=2|PaperLength=1000|PaperWidth=1000|Scale=100|PaperSource=15|PrintQuality=600|MediaType=1|DitherType=10|PaperKind=Letter|PrintScaleMode=1
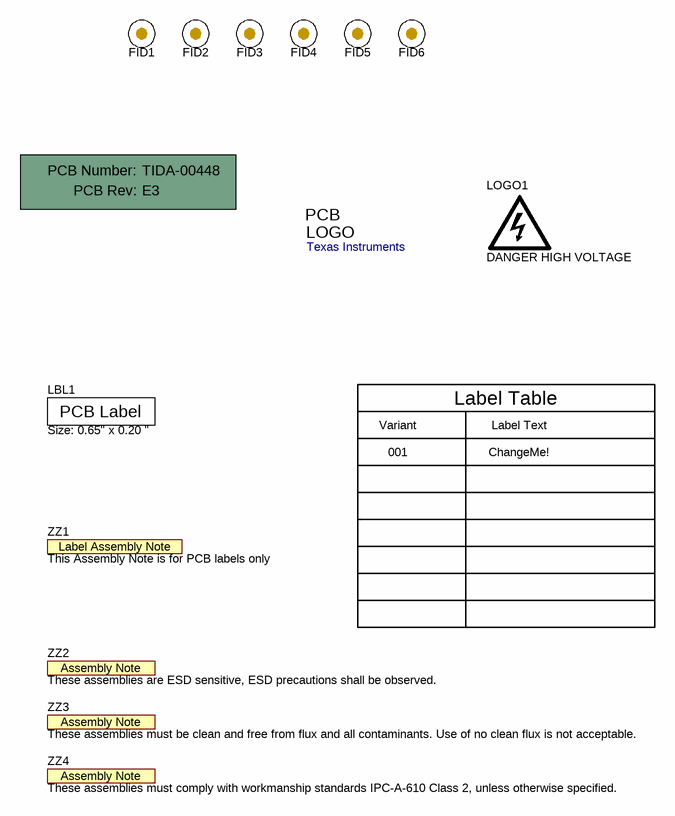
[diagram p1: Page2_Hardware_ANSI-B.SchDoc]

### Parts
!PCB1  Printed Circuit Board  (value not drawn)  (mechanical)
FID1  Fiducial  [Fiducial10-20]  (value not drawn)
FID2  Fiducial  [Fiducial10-20]  (value not drawn)
FID3  Fiducial  [Fiducial10-20]  (value not drawn)
FID4  Fiducial  [Fiducial10-20]  (value not drawn)
FID5  Fiducial  [Fiducial10-20]  (value not drawn)
FID6  Fiducial  [Fiducial10-20]  (value not drawn)
LBL1  Size: 0.65" x 0.20 "  [Label_650x200]
LOGO1  DANGER HIGH VOLTAGE  [IEC_HighVoltage_Small]  (no BOM)
Logo2  Texas Instruments  [TI_Stacked_Overlay_Small]  (no BOM)
ZZ1  This Assembly Note is for PCB labels only  [AssemblyNoteLabel]  (no BOM)
ZZ2  These assemblies are ESD sensitive, ESD precautions shall be observed.  [AssemblyNote]  (no BOM)
ZZ3  These assemblies must be clean and free from flux and all contaminants. Use of no clean flux is not acceptable.  [AssemblyNote]  (no BOM)
ZZ4  These assemblies must comply with workmanship standards IPC-A-610 Class 2, unless otherwise specified.  [AssemblyNote]  (no BOM)

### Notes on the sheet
- Variant
- Label Table
- Label Text
- 001
- ChangeMe!

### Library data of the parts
!PCB1 = PCB: Manufacturer: Any; PartNumber: TIDA-00448; SymbolCreator: a0412235
FID1-FID6 = Fiducial: Fiducial mark.  There is nothing to buy or mount.; SymbolCreator: codlsc
LBL1 = THT-14-423-10: Thermal Transfer Printable Labels, 0.650" W x 0.200" H - 10,000 per roll; Manufacturer: Brady; SymbolCreator: a0412235; CompType: Label
LOGO1 = IEC_HighVoltage: IEC 61010-1 High Voltage Warning; SymbolCreator: a0412235
Logo2 = TI_Logo: Texas Instrument Corporate Signature; SymbolCreator: a0412235
ZZ1 = AssemblyNoteLabel: SymbolCreator: a0412235
ZZ2-ZZ4 = AssemblyNote: SymbolCreator: codlsc

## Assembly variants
001: not fitted C14 C39 D7 D17 Q5 R13 R16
